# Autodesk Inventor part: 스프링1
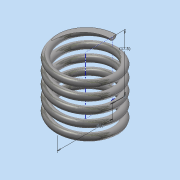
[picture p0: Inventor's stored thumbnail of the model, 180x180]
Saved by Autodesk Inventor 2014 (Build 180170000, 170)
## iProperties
Created: 2016-03
Part Number: 스프링1
Material: 스테인레스 스틸
Document SubType Name: Modeling
Designer: SCD-A13
Density: 8.08 g/cm^3
Appearance: 반연마
Mass: 6.61435 g
Surface Area: 16.696 cm^2
Volume: 0.818608 cm^3
Author: SCD-A13
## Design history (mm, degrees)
sketch "스케치1"
  geometry: L1 (0, 17.5)-(8.5, 17.5); L2 (8.5, 17.5)-(8.5, 0); L3 (8.5, 0)-(0, 0); L4 (0, 0)-(0, 17.5); C1 r 1 at (8.5, 0); 1 further point
  constraints: 8 end point, 2 coincident, 2 parallel, 1 centre point, 1 horizontal, 1 perpendicular
  dimensions: "d0" = 2 diameter of C1; "d1" = 17 diameter of L2 L4; "d2" = 17.5 distance between parallel lines of L1 L3 (derived)
feature "코일1" pitch "d3" = 10; turns "d5" = 5; dims "d4" = 17.5 (= d2), "d6" = 0, angle "d7" = 90 deg, angle "d8" = 90 deg, "d9" = 0, "d10" = 0
node "작업 평면1"
sketch "스케치2"
  geometry: L1 (1, 0)-(-1, 0) reference; 1 further point
  constraints: 1 horizontal alignment
extrude "돌출1" cut sketch "스케치2" stored distance "d12" = 10; taper "d13" = 0 deg
node "작업 평면2"
sketch "스케치3"
  geometry: L1 (9.5, 0)-(7.5, 0) reference; 1 further point
  constraints: 1 horizontal alignment
extrude "돌출2" cut sketch "스케치3" stored distance "d15" = 10; taper "d16" = 0 deg
node "솔리드1"
node "절단 모서리 투영1"
node "절단 모서리 투영2"
other parameters: "d11" = 0, "d14" = 0
